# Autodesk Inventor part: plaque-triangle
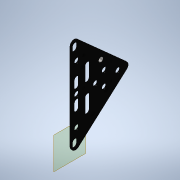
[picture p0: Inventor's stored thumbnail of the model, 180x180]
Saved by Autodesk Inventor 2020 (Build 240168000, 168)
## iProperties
Created: 2021-10
Part Number: plaque-triangle
Material: Aluminium 6061
Document SubType Name: Modeling
Designer: bruno
Density: 3.91951 g/cm^3
Appearance: Noir
Mass: 5 g
Surface Area: 29.1335 cm^2
Volume: 1.27567 cm^3
Author: bruno
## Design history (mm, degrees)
sketch "Esquisse1"
  geometry: L1 (4, -0.038)-(44, -0.038); L2 (14.49, -9.788)-(19.24, -9.788); L3 (19.413, -2.288)-(23.913, -2.288); L4 (23.913, -5.788)-(19.413, -5.788); L5 (23.49, -9.788)-(19.24, -9.788); L6 (33.053, -5.788)-(37.553, -5.788); L7 (37.553, -2.288)-(33.053, -2.288); L8 (3.777, -0.038)-(-1.51, -0.038); L9 (-3.746, -5.038)-(26.254, -38.579); L10 (30.726, -38.579)-(60.726, -5.038); L11 (58.49, -0.038)-(44, -0.038); L12 (28.49, -36.579)-(28.49, 3.455); L13 (42.49, -9.788)-(37.74, -9.788); L14 (33.49, -9.788)-(37.74, -9.788); L15 (0.726, -1.038)-(-1.274, -1.038); L16 (0.726, -4.538)-(-1.274, -4.538); L17 (56.253, -1.038)-(58.253, -1.038); L18 (56.253, -4.538)-(58.253, -4.538); L19 (4, -0.038)-(3.777, -0.038); L20 (14.49, -13.288)-(23.49, -13.288); L21 (33.49, -13.288)-(42.49, -13.288); C1 r 1.75 at (48.49, -4.038); C2 r 1.75 at (8.49, -4.038); C3 r 1.75 at (28.483, -4.038); C4 r 1.75 at (28.49, -17.038); C5 r 1.75 at (28.49, -32.538); C6 r 1.75 at (33.49, -23.038); C7 r 1.75 at (23.49, -23.038); C8 r 1.5 at (40.99, -20.538); A1 r 1.75 centre (37.553, -4.038) between (37.553, -5.788) and (37.553, -2.288); A2 r 1.75 centre (23.913, -4.038) between (23.913, -5.788) and (23.913, -2.288); A3 r 1.75 centre (19.413, -4.038) between (19.413, -2.288) and (19.413, -5.788); A4 r 1.75 centre (14.49, -11.538) between (14.49, -9.788) and (14.49, -13.288); A5 r 1.75 centre (33.053, -4.038) between (33.053, -2.288) and (33.053, -5.788); A6 r 1.75 centre (23.49, -11.538) between (23.49, -13.288) and (23.49, -9.788); A7 r 3 centre (28.49, -36.579) between (26.254, -38.579) and (30.726, -38.579); A8 r 3 centre (58.49, -3.038) between (60.726, -5.038) and (58.49, -0.038); A9 r 3 centre (-1.51, -3.038) between (-1.51, -0.038) and (-3.746, -5.038); A10 r 1.75 centre (33.49, -11.538) between (33.49, -9.788) and (33.49, -13.288); A11 r 1.75 centre (42.49, -11.538) between (42.49, -13.288) and (42.49, -9.788); A12 r 1.75 centre (-1.274, -2.788) between (-1.274, -1.038) and (-1.274, -4.538); A13 r 1.75 centre (0.726, -2.788) between (0.726, -4.538) and (0.726, -1.038); A14 r 1.75 centre (56.253, -2.788) between (56.253, -1.038) and (56.253, -4.538); A15 r 1.75 centre (58.253, -2.788) between (58.253, -4.538) and (58.253, -1.038); 11 further points
  constraints: 42 end point, 31 point on circle, 23 centre point, 15 symmetric about line, 11 point on line, 9 tangent, 5 horizontal, 2 coincident, 2 equal radius, 2 parallel, 1 collinear, 1 midpoint, 1 perpendicular, 5 other
  dimensions: "d0" = 3.5 diameter of C1; "d1" = 3.5 diameter of C2; "d2" = 3.5 diameter of C3; "d3" = 3.5 diameter of A1; "d4" = 3.5 diameter of A5; "d5" = 4.5 distance of A1.centre A5.centre; "d6" = 3.5 diameter of A6; "d7" = 3 radius of A7; "d8" = 60 distance of A8.centre A9.centre; "d9" = 45 distance of L12.start A8.centre; "d10" = 45 distance of L12.start A9.centre; "d11" = 10 horizontal distance of point (8.49, -4.038) A9.centre; "d12" = 10 horizontal distance of A8.centre C1.centre; "d13" = 9 distance of A6.centre A4.centre; "d14" = 5 distance from line of L12 A6.centre; "d15" = 4 distance between parallel lines of L5 L4; "d16" = 2.25 distance between parallel lines of L1 L7; "d17" = 2.25 distance between parallel lines of L1 L3; "d18" = 3.5 diameter of C4; "d19" = 13 distance of C4.centre C3.centre; "d20" = 3.5 diameter of C5; "d21" = 15.5 distance of C5.centre C4.centre; "d22" = 3.5 diameter of C6; "d23" = 5 distance from line of L12 C6.centre; "d24" = 3.5 diameter of A13; "d25" = 3.5 diameter of A12; "d26" = 2 distance of A12.centre A13.centre; "d27" = 1 distance between parallel lines of L8 L15; "d28" = 6 vertical distance of C4.centre C6.centre; "d29" = 3 diameter of C8; "d30" = 12.5 distance from line of C8.centre L12; "d32" = 4 distance between parallel lines of L14 L6; "d33" = 4 distance from line of L1 C3.centre; "d41" = 12 vertical distance of C5.centre C8.centre
extrude "Extrusion3" join sketch "Esquisse1" distance "d42" = 1; taper "d43" = 0 deg
node "Plan de construction1"
sketch "Esquisse3"
  geometry: C1 r 1.5 at (-20.538, 40.99) reference; C2 r 3 at (-20.538, 40.99); C3 r 1.5 at (-20.538, 40.99) reference; 1 further point
  constraints: 2 coincident, 1 centre point
  dimensions: "d36" = 6 diameter of C2
extrude "Extrusion2" join sketch "Esquisse3" distance "d37" = 1.5; taper "d38" = 0 deg
node "Solide1"
